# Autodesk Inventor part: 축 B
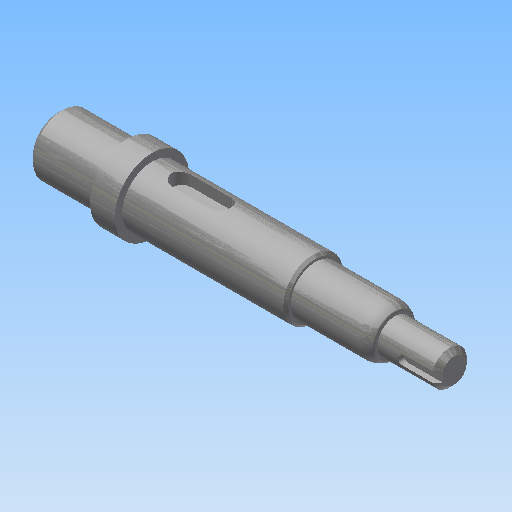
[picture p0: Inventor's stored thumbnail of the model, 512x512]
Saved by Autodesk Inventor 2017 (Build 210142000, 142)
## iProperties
Created: 2020-04
Part Number: 축 B
Material: 강철, 연강
Document SubType Name: Modeling
Designer: mduedu
Density: 7.86 g/cm^3
Appearance: 강철
Mass: 60.8598 g
Surface Area: 31.2859 cm^2
Volume: 7.74298 cm^3
Author: mduedu
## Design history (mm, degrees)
sketch "스케치1"
  geometry: L1 (0, 0)-(14, 0); L2 (14, 0)-(14, 6); L3 (14, 6)-(0, 6); L4 (0, 6)-(0, 0); L5 (14, 0)-(19, 0); L6 (19, 0)-(19, 7.5); L7 (19, 7.5)-(14, 7.5); L8 (14, 7.5)-(14, 0); L9 (19, 0)-(52, 0); L10 (52, 0)-(52, 6); L11 (52, 6)-(19, 6); L12 (19, 6)-(19, 0); L13 (52, 0)-(68, 0); L14 (68, 0)-(68, 5); L15 (68, 5)-(52, 5); L16 (52, 5)-(52, 0); L17 (68, 0)-(80, 0); L18 (80, 0)-(80, 3.5); L19 (80, 3.5)-(68, 3.5); L20 (68, 3.5)-(68, 0)
  constraints: 40 end point, 10 parallel, 5 horizontal, 5 perpendicular
  dimensions: "d0" = 80 distance between parallel lines of L18 L4; "d2" = 14 distance of L2.end L3.end; "d3" = 5 distance of L6.end L7.end; "d5" = 7 diameter of L19 L17; "d6" = 10 diameter of L15 L13; "d7" = 12 diameter of L11 L9; "d8" = 12 diameter of L3 L1; "d9" = 15 diameter of L7 L5; "d35" = 16 distance of L14.end L15.end; "d36" = 52 distance between parallel lines of L10 L4
revolve "회전1" sketch "스케치1" stored, may be unused: angle "d11" = 90 deg
sketch "스케치2"
  geometry: L1 (0, 6)-(0, -6) reference; L2 (0, -6)-(-14, -6) reference; L3 (-14, -6)-(-14, -7.5) reference; L4 (-14, -7.5)-(-19, -7.5) reference; L5 (-19, -7.5)-(-19, -6) reference; L6 (-19, -6)-(-52, -6) reference; L7 (-52, -6)-(-52, -5) reference; L8 (-52, -5)-(-68, -5) reference; L9 (-68, -5)-(-68, -3.5) reference; L10 (-68, -3.5)-(-80, -3.5) reference; L11 (-80, -3.5)-(-80, 3.5) reference; L12 (-80, 3.5)-(-68, 3.5) reference; L13 (-68, 3.5)-(-68, 5) reference; L14 (-68, 5)-(-52, 5) reference; L15 (-52, 5)-(-52, 6) reference; L16 (-52, 6)-(-19, 6) reference; L17 (-19, 6)-(-19, 7.5) reference; L18 (-19, 7.5)-(-14, 7.5) reference; L19 (-14, 7.5)-(-14, 6) reference; L20 (-14, 6)-(0, 6) reference; L21 (-80, 3.5)-(-72, 3.5); L22 (-72, 3.5)-(-72, 2.3); L23 (-72, 2.3)-(-80, 2.3); L24 (-80, 2.3)-(-80, 3.5); 1 further point
  constraints: 8 end point, 2 parallel, 1 horizontal, 1 perpendicular
  dimensions: "d37" = 8 distance of L22.end L23.end; "d38" = 1.2 distance of L21.end L22.end
extrude "돌출1" cut sketch "스케치2" stored distance "d14" = 2; taper "d15" = 0 deg
fillet "모깎기1" dims "d16" = 1
sketch "스케치3"
  geometry: L1 (0, -6)-(0, 6) reference; L2 (0, 6)-(14, 6) reference; L3 (14, 6)-(14, 7.5) reference; L4 (14, 7.5)-(19, 7.5) reference; L5 (19, 7.5)-(19, 6) reference; L6 (19, 6)-(52, 6) reference; L7 (52, 6)-(52, 5) reference; L8 (52, 5)-(68, 5) reference; L9 (68, 5)-(68, 3.5) reference; L10 (68, 3.5)-(80, 3.5) reference; L11 (80, 3.5)-(80, -3.5) reference; L12 (80, -3.5)-(68, -3.5) reference; L13 (68, -3.5)-(68, -5) reference; L14 (68, -5)-(52, -5) reference; L15 (52, -5)-(52, -6) reference; L16 (52, -6)-(19, -6) reference; L17 (19, -6)-(19, -7.5) reference; L18 (19, -7.5)-(14, -7.5) reference; L19 (14, -7.5)-(14, -6) reference; L20 (14, -6)-(0, -6) reference; L21 (23, 6)-(35, 6); L22 (35, 6)-(35, 3.5); L23 (35, 3.5)-(23, 3.5); L24 (23, 3.5)-(23, 6); 1 further point
  constraints: 8 end point, 2 parallel, 1 horizontal, 1 perpendicular, 1 point on line
  dimensions: "d17" = 12 distance of L22.end L23.end; "d18" = 2.5 distance of L21.end L22.end; "d19" = 4 distance from line of L24 L4.end
extrude "돌출2" cut sketch "스케치3" stored distance "d20" = 4; taper "d21" = 0 deg
fillet "모깎기2" dims "d22" = 2
chamfer "모따기1" distance "d23" = 1; stored, may be unused: second distance "d24" = 2, angle "d25" = 45 deg
chamfer "모따기2" distance "d26" = 0.5; stored, may be unused: second distance "d27" = 2, angle "d28" = 45 deg
fillet "모깎기3" dims "d29" = 0.3
chamfer "모따기3" distance "d30" = 1.39; stored, may be unused: second distance "d31" = 2, angle "d32" = 30 deg
fillet "모깎기4" dims "d33" = 4, "d34" = 0.5
node "솔리드1"
node "절단 모서리 투영2"
node "절단 모서리 투영3"
